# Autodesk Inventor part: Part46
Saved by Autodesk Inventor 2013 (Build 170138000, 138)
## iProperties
Created: 2012-07
Part Number: Part46
Material: Generic
Document SubType Name: Modeling
Designer: Paul
Density: 1 g/cm^3
Author: Paul
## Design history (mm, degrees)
node "User Library-Arduino Mega.SAT1"
body "Solid1"
node "Base1"
